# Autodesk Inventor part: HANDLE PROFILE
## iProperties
Created: 2012-06
Part Number: HANDLE PROFILE
Material: Aluminum-6061
Description: HANDLE PROFILE
Document SubType Name: Modeling
Designer: Administrator
Stock Number: 20.1045 HANDLE PROFILE
Density: 2.71 g/cm^3
FINISH: CLEAR ANODIZED
Author: Administrator
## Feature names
1. Extrusion1
